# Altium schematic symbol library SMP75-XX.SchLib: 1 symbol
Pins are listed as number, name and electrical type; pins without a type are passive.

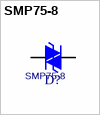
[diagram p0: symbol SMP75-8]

## SMP75-8
designator D?
footprint ST_SMBB
pins: 1, 2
